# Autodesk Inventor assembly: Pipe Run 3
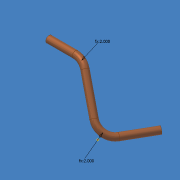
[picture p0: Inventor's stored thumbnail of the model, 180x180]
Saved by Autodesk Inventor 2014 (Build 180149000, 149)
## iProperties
Company: Autodesk, Inc.
TPVersion: 11.0.2
Shininess: 64.0
Length Units: 11272
Angle Units: 11279
Time Units: 11290
Mass Units: 11286
Length Display Precision: 3
Angle Display Precision: 2
Compacted: True
Name: ASTM B 88-ASME B16.22 - Soldered Copper Tubing
ActiveState: True
PipeType: Tubing
Material: UnInitValue
Standard: UnInitValue
FittingMaterial: UnInitValue
FittingStandard: UnInitValue
RouteDirection90: UnInitValue
RouteDirection45: UnInitValue
DiameterType: Nominal
Diameter: 1/2
Schedule: L
OD: UnInitValue
ID: UnInitValue
Ending: UnInitValue
IntermediateSegmentsMin: 0.000 in
IntermediateSegmentsMax: 100.000 in
IntermediateSegmentsInc: 0.100 in
TerminationSegmentsMin: 0.000 in
TerminationSegmentsMax: 100.000 in
TerminationSegmentsInc: 0.100 in
RoundUpValue: UnInitValue
DefaultBendRadius: 2.000 in
PipingComponentColor: As Material
PipeKey: v3#44b182c9-4bce-4825-bb4d-596143122252#7
CouplingKey: v3#0dc1ae02-7bbf-4ccf-8498-581434b0a765#3
Elbow90Key: UnInitValue
Elbow45Key: UnInitValue
_ComponentInfo: <CS><C N="Pipe" R="0.793750" OR="0.793750" IR="0.692150" PL="PL" PartType="pipe" SymKey="" PN="ASTM B 88 Tube 1/2 - Type L"><CO N="1"><FE V="0"/><FD V="0"/><ET 
BendRadius: UnInitValue
StartFittingKey: UnInitValue
EndFittingKey: UnInitValue
SuppressStartFitting: UnInitValue
SuppressEndFitting: UnInitValue
UseSubASM: UnInitValue
FlangeKey: UnInitValue
Gap: UnInitValue
GasketKey: UnInitValue
IsButtWelded: UnInitValue
IsFlanged: UnInitValue
MixedUnits: UnInitValue
ShowGap: UnInitValue
UseFlangsForCouplings: UnInitValue
Angle: UnInitValue
ElbowCustomKey: UnInitValue
IsSelfDraining: UnInitValue
Part Number: Pipe Run 3
Document SubType Name: Tube & Pipe
Created: 2003-10
Designer: Autodesk, Inc.
Manufacturer: Standard
Standards Organization: Custom
Mass: 186.829 g
Surface Area: 412.329 cm^2
Volume: 20.8981 cm^3
Density: 8.94 g/cm^3
Density: 0.0
Volumn: 0.0
Area: 0.0
PropertySet Name: Model Information
Control State: 0
Master: False
Checked Out: False
Author: Autodesk, Inc.
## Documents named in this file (3)
- C:\Users\iTools\Desktop\tutorial files\Tube and Pipe\Accumulator\AIP\Run2\Tube Run2.iam
- C:\Users\iTools\Desktop\tutorial files\Tube and Pipe\Accumulator\AIP\Run2\piroute.1067629144834.ipt
- C:\Users\iTools\Desktop\tutorial files\Tube and Pipe\Accumulator\AIP\Run2\pisweep.1173805126414.ipt
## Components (2 placed, 2 different names)
1. Pipe Route
2. Tube Segment 5:1
